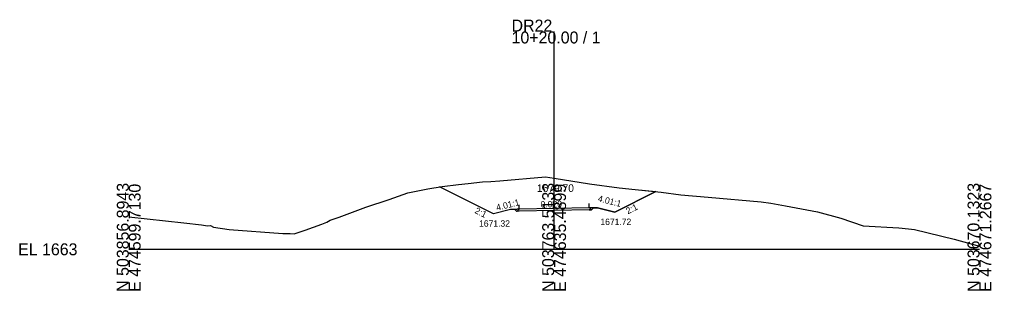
# Model space of a CAD drawing. Extents: x -26 to 1203, y -10 to 9633.
# Drawn here: x -25.7 to 202.8, y 490.3 to 554 of the extents above; entities that cross this region are included whole.
import ezdxf

# ---------------------------------------------------------------- set-up
doc = ezdxf.new("R2010")
doc.units = 0
for name, color, linetype in [('Exist Cross Section Cell', 7, 'Continuous'), ('Exist XS Center Line Elevation Label', 7, 'Continuous'), ('Exist XS Ground Line', 7, 'Continuous'), ('Prop XS Ditch Slope Text', 7, 'Continuous'), ('Prop XS Ditch Standard Text', 7, 'Continuous'), ('Prop XS Earthwork Shape', 7, 'Continuous'), ('Prop XS EOT Tick Mark', 7, 'Continuous'), ('Prop XS Finish Grade', 7, 'Continuous'), ('Prop XS Finish Grade Earthwork', 7, 'Continuous'), ('Prop XS Finish Grade Pavement', 7, 'Continuous'), ('Prop XS Pvmt Edge Slope', 7, 'Continuous'), ('Prop XS SE Text', 7, 'Continuous'), ('Prop XS Shoulder Borrow Shape', 7, 'Continuous'), ('Prop XS Side Slope Text', 7, 'Continuous'), ('Prop XS Subgrade Earthwork', 7, 'Continuous'), ('Scratch_Level_5', 7, 'Continuous')]:
    doc.layers.add(name, color=color, linetype=linetype)

msp = doc.modelspace()

# ---------------------------------------------------------------- linework, layer by layer
at = {"layer": 'Exist Cross Section Cell'}
for p, q in [((100, 500), (100, 551.18)), ((0, 500), (100, 500)), ((100, 500), (200, 500))]:
    msp.add_line(p, q, dxfattribs=at)
at = {"layer": 'Exist XS Ground Line'}
msp.add_lwpolyline([(0, 507.6), (12.92, 506.22), (17.13, 505.79), (18.55, 505.48), (19.19, 505.6), (19.94, 505.19), (23.6, 504.65), (36.21, 503.74), (37.95, 503.68), (38.89, 503.6), (41.48, 504.53), (45.37, 505.94), (46.56, 506.35), (47.37, 506.81), (49.46, 507.55), (55.74, 509.88), (61.21, 511.74), (65.63, 513.25), (70.29, 514.22), (73.7, 514.78), (77.52, 515.2), (79.77, 515.45), (83.2, 515.82), (85.13, 515.9), (87.23, 516.06), (97.95, 517.03), (100, 516.7), (108.36, 515.39), (115.31, 514.42), (119.08, 514.09), (125.14, 513.42), (129.79, 512.82), (136.24, 512.24), (148.66, 511.19), (150.92, 510.86), (154.37, 510.23), (161.92, 508.81), (167.4, 507.35), (172.63, 505.53), (181.05, 505.07), (183.34, 504.85), (184.76, 504.64), (194.05, 502.35), (200, 500.72)], dxfattribs=at)
at = {"layer": 'Prop XS Earthwork Shape'}
msp.add_lwpolyline([(91.22, 508.92), (90.75, 509.39), (89.77, 509.32), (85.76, 508.32), (73.03, 514.67), (73.7, 514.78), (77.52, 515.2), (79.77, 515.45), (83.2, 515.82), (85.13, 515.9), (87.23, 516.06), (97.95, 517.03), (100, 516.7), (108.36, 515.39), (115.31, 514.42), (119.08, 514.09), (123.92, 513.56), (114.24, 508.72), (110.23, 509.72), (109.25, 509.76), (108.76, 509.27), (108.23, 509.26), (100, 509.1), (91.77, 508.93)], close=True, dxfattribs=at)
at = {"layer": 'Prop XS EOT Tick Mark'}
for p, q in [((91.77, 509.48), (91.77, 510.48)), ((108.23, 509.8), (108.23, 510.8))]:
    msp.add_line(p, q, dxfattribs=at)
at = {"layer": 'Prop XS Finish Grade'}
for p, q in [((108.23, 509.8), (109.25, 509.76)), ((91.77, 509.48), (90.75, 509.39))]:
    msp.add_line(p, q, dxfattribs=at)
at = {"layer": 'Prop XS Finish Grade Earthwork'}
for p, q in [((85.76, 508.32), (73.03, 514.67)), ((114.24, 508.72), (123.92, 513.56)), ((109.25, 509.76), (110.23, 509.72)), ((110.23, 509.72), (114.24, 508.72)), ((89.77, 509.32), (85.76, 508.32)), ((90.75, 509.39), (89.77, 509.32))]:
    msp.add_line(p, q, dxfattribs=at)
at = {"layer": 'Prop XS Finish Grade Pavement'}
for p, q in [((91.77, 509.48), (100, 509.64)), ((100, 509.64), (108.23, 509.8))]:
    msp.add_line(p, q, dxfattribs=at)
at = {"layer": 'Prop XS Pvmt Edge Slope'}
for p, q in [((108.23, 509.8), (108.76, 509.27)), ((91.77, 509.48), (91.22, 508.92))]:
    msp.add_line(p, q, dxfattribs=at)
at = {"layer": 'Prop XS Shoulder Borrow Shape'}
for points in [[(108.76, 509.27), (109.25, 509.76), (108.23, 509.8)], [(91.77, 509.48), (91.22, 508.92), (90.75, 509.39)]]:
    msp.add_lwpolyline(points, close=True, dxfattribs=at)
at = {"layer": 'Prop XS Subgrade Earthwork'}
for p, q in [((108.76, 509.27), (109.25, 509.76)), ((91.22, 508.92), (90.75, 509.39)), ((91.77, 508.93), (91.22, 508.92)), ((100, 509.1), (91.77, 508.93)), ((108.23, 509.26), (100, 509.1)), ((108.23, 509.26), (108.76, 509.27))]:
    msp.add_line(p, q, dxfattribs=at)
at = {"layer": 'Scratch_Level_5'}
msp.add_lwpolyline([(0, 507.6), (12.92, 506.22), (17.13, 505.79), (18.55, 505.48), (19.19, 505.6), (19.94, 505.19), (23.6, 504.65), (36.21, 503.74), (37.95, 503.68), (38.89, 503.6), (41.48, 504.53), (45.37, 505.94), (46.56, 506.35), (47.37, 506.81), (49.46, 507.55), (55.74, 509.88), (61.21, 511.74), (65.63, 513.25), (70.29, 514.22), (73.7, 514.78), (77.52, 515.2), (79.77, 515.45), (83.2, 515.82), (85.13, 515.9), (87.23, 516.06), (97.95, 517.03), (100, 516.7), (108.36, 515.39), (115.31, 514.42), (119.08, 514.09), (125.14, 513.42), (129.79, 512.82), (136.24, 512.24), (148.66, 511.19), (150.92, 510.86), (154.37, 510.23), (161.92, 508.81), (167.4, 507.35), (172.63, 505.53), (181.05, 505.07), (183.34, 504.85), (184.76, 504.64), (194.05, 502.35), (200, 500.72)], dxfattribs=at)

# ---------------------------------------------------------------- texts
at = {"layer": 'Exist Cross Section Cell'}
for s, p in [('DR22', (90, 551.18)), ('10+20.00 / 1', (90, 548.38)), ('EL 1663', (-26, 498.6))]:
    msp.add_text(s, height=2.8, dxfattribs=at).set_placement(p)
for s, p in [('N 503856.8943', (0, 490)), ('E 474599.7130', (2.8, 490)), ('N 503763.5133', (100, 490)), ('E 474635.4899', (102.8, 490)), ('N 503670.1323', (200, 490)), ('E 474671.2667', (202.8, 490))]:
    msp.add_text(s, height=2.8, rotation=90, dxfattribs=at).set_placement(p)
at = {"layer": 'Exist XS Center Line Elevation Label'}
msp.add_text('1679.70', height=1.8, dxfattribs=at).set_placement((95.96, 513.47))
at = {"layer": 'Prop XS Ditch Slope Text'}
for rotation, p in [(345.988, (110.18, 511.28)), (14.0066, (86.58, 509.04))]:
    msp.add_text('4.01:1', height=1.5, rotation=rotation, dxfattribs=at).set_placement(p)
at = {"layer": 'Prop XS Ditch Standard Text'}
for s, p in [('1671.32', (82.37, 505.32)), ('1671.72', (110.89, 505.72))]:
    msp.add_text(s, height=1.5, dxfattribs=at).set_placement(p)
at = {"layer": 'Prop XS SE Text'}
msp.add_text('0.020', height=1.5, rotation=1.1458, dxfattribs=at).set_placement((96.84, 509.81))
at = {"layer": 'Prop XS Side Slope Text'}
for rotation, p in [(333.4854, (81.19, 508.6)), (26.5237, (117.34, 508.21))]:
    msp.add_text('2:1', height=1.5, rotation=rotation, dxfattribs=at).set_placement(p)

doc.saveas('drawing.dxf')
